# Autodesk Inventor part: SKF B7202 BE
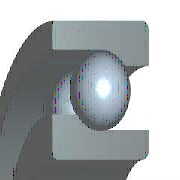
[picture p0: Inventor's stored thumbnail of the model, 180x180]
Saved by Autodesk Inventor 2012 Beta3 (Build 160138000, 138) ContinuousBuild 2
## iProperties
Created: 2010-02
Part Number: SKF B7202 BE
Material: Steel, Mild
Description: Single row angular contact ball bearings SKF
Document SubType Name: Modeling
Standard: SKF B
Designer: Thom Tremblay
Language: en-US
Size Designation: SKF B7202 BE
Categories: <MemberInstance><Categories><Category DisplayName="Shaft Parts" InternalName="7f7aeb1f-a693-4053-b835-cee3144e0d98" Mnemonic="SHFT"><Category DisplayName="Beari
Density: 7.86 g/cm^3
IsCustomPart: 0
Author: Thom Tremblay
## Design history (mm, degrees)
node "WorkPlane1"
workplane "Work Plane2"
node "WorkPlane2"
node "Sketch1"
node "WorkPoint1"
node "Sketch2"
node "WorkPoint3"
node "Sketch3"
node "WorkPoint2"
node "WorkAxis1"
node "Sketch7"
workaxis "Work Axis2"
pattern_circular "PolarArray1" dims angle "d18" = 360 deg
fillet "Fillet1" dims "d19" = 0.3 (= r1)
fillet "Fillet2" dims "d20" = 0.6 (= r)
body "Solid1"
revolve "Revolution1" stored, may be unused: angle "d7" = 360 deg
revolve "Revolution2" stored, may be unused: angle "d12" = 360 deg
revolve "Revolution3" stored, may be unused: angle "d15" = 360 deg
sketch "Sketch4"
  geometry: L1 (17.5, 0)-(7.5, 0); L2 (17.5, 11)-(17.5, 0); L3 (7.5, 11)-(17.5, 11); L4 (7.5, 0)-(7.5, 11); L5 (0, -3.737)-(0, 15.931); L6 (0, -3.737)-(0, 15.931); L7 (0, -7.671)-(0, 19.865) reference; L8 (-4.7, 0)-(28.2, 0) reference
  constraints: 12 end point, 3 vertical, 2 collinear, 2 horizontal
  dimensions: "d2" = 7.5 horizontal distance of L3.start L5.end (= 0.5 x Diam); "d4" = 17.5 horizontal distance of L2.start L5.end (= 0.5 x DD); "d6" = 11 distance of L1.end L3.start (= B)
sketch "Sketch5"
  geometry: L1 (15.5, 11)-(10.7, 11); L2 (15.5, 5.5)-(15.5, 11); L3 (14.3, 0)-(14.3, 3.1); L4 (9.5, 0)-(14.3, 0); L5 (9.5, 5.5)-(9.5, 0); L6 (10.7, 11)-(10.7, 7.9); L7 (17.5, 0)-(-17.5, 0) reference; L8 (17.5, 11)-(-17.5, 11) reference; L9 (0, 40.963)-(0, -26.963); L10 (0, -40.549)-(0, 54.549) reference; A1 r 3 centre (12.5, 5.5) between (14.3, 3.1) and (15.5, 5.5); A2 r 3 centre (12.5, 5.5) between (10.7, 7.9) and (9.5, 5.5); A3 r 3 centre (12.5, 5.5) between (15.5, 5.5) and (10.7, 7.9)
  constraints: 14 end point, 7 point on circle, 4 vertical, 3 centre point, 3 collinear, 2 horizontal, 2 tangent, 1 coincident, 1 concentric
  dimensions: "d9" = 5.5 vertical distance of A2.centre L3.start (= 0.5 x B); "d11" = 6 diameter of A3 (= msp_mdtdk); "d21" = 25 diameter of A1.centre L9 (= msp_mdtds); "d22" = 21.4 diameter of L6 L9 (= msp_md); "d23" = 28.6 diameter of L3 L9 (= msp_vd)
sketch "Sketch6"
  geometry: L1 (12.5, 2.5)-(12.5, 8.5); L2 (12.5, 13.675)-(12.5, -2.513); L3 (17.5, 0)-(-17.5, 0) reference; L4 (12.5, 13.675)-(12.5, -2.513); L5 (15.5, 5.5)-(-15.5, 5.5) reference; A1 r 3 centre (12.5, 5.5) between (12.5, 2.5) and (12.5, 8.5); A2 r 3 centre (12.5, 5.5) between (10.7, 7.9) and (9.5, 5.5) reference
  constraints: 6 end point, 4 point on line, 2 point on circle, 1 centre point, 1 concentric, 1 vertical
  dimensions: "d14" = 3 radius of A1 (= 0.5 x msp_mdtdk)
other parameters: "Diam" = 15 [user parameter; used in 3 equation terms], "DD" = 35 [user parameter; used in 3 equation terms], "B" = 11 [user parameter; used in 3 equation terms], "r" = 0.6 [user parameter; used in 1 equation term], "msp_mdtdk" = 6 (= -0.3 x Diam + 0.3 x DD) [user parameter; used in 5 equation terms], "msp_mdtds" = 25 (= 0.5 x DD + 0.5 x Diam) [user parameter; used in 4 equation terms], "msp_md" = 21.4 (= msp_mdtds - 0.6 x msp_mdtdk) [user parameter; used in 1 equation term], "msp_vd" = 28.6 (= msp_mdtds + 0.6 x msp_mdtdk) [user parameter; used in 1 equation term], "r1" = 0.3 [user parameter; used in 1 equation term], "d0" = -11 (computed from B), "d3" = 23.5 (derived), "d5" = 14 (derived), "d8" = 7 (derived), "d10" = 8.1 (derived), "d13" = 4.05 (derived), "d26" = 0, "d27" = 0, "d28" = 0, "d29" = 0, "d30" = 0
